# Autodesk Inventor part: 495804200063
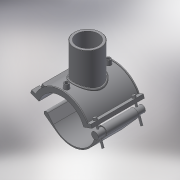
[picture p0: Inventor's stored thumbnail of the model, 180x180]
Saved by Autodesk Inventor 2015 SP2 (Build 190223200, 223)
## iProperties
Created: 2017-07
Part Number: 495804200063
Material: Generic
Description: PLASSON BRANCH SADDLE 200-63
Document SubType Name: Modeling
Designer: KIM
Density: 1 g/cm^3
Appearance: Default
Author: KIM
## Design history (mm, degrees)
derived "495804.ipt"
feature "Solid1::495804.ipt"
feature "Solid2::495804.ipt"
tag "TaggingFeature1"
body "Solid1"
body "Solid2"
other parameters: "d2" = 262.6, "d4" = 176, "d5" = 0, "d6" = 0.1, "d8" = 0, "d19" = 6, "d20" = 6, "d21" = 105.6, "d23" = 0, "d24" = 52.8, "d26" = 0, "d27" = 3, "d28" = 3, "d29" = 3, "d30" = 66.66667, "d31" = 6, "d32" = 0, "d33" = 0, "d34" = 0.6, "d40" = 121.68, "d41" = 69.3, "d43" = 0, "d45" = 0, "d47" = 219, "d48" = 63, "d50" = 0, "d70" = 15, "d72" = 0, "d73" = 6, "d75" = 5, "d76" = 0, "d79" = 15, "d80" = 70.4, "d82" = 5 deg, "d84" = 4, "d85" = 14, "d86" = 0, "d87" = 3, "d88" = 0, "d89" = 1, "d90" = 1, "d91" = 140.8, "d92" = 0, "d93" = 0.5, "d94" = 105.26316, "d96" = 238.68, "d97" = 3.52, "d98" = 0, "d102" = 1.89, "d103" = 50.4, "d105" = 0, "d109" = -34, "d117" = 0.63, "d120" = 140 deg, "d121" = 24.228, "d122" = 20 deg, "d123" = 468, "d124" = 140.4, "d126" = 0, "d150" = 36, "d159" = 6.8, "d161" = 5, "d162" = 105.6, "d163" = 0, "d168" = 106.36364, "d173" = 1, "d176" = 20 deg, "d177" = 14, "d178" = 34, "d180" = 0, "d185" = 57.2, "d186" = 57.2, "d187" = 117, "d188" = 10.2, "d189" = 14, "d190" = 0, "d191" = 175.5, "d200" = 17, "d202" = 0, "d216" = 158.4, "d217" = 0, "d221" = 65.12, "d222" = 14, "d223" = 8.4, "d225" = 8.4, "d227" = 28.8, "d230" = 124, "d236" = 20 deg, "d237" = 124, "d238" = 20 deg, "d239" = 14, "B_" = 202, "H_" = 102, "L_" = 176, "d_t" = 6, "d_1" = 63, "H_1" = 85, "d1" = 234, "d148" = 5, "d160" = 5
